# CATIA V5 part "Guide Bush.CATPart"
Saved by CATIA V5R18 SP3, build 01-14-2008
Part number: Moving Part01
Bounding box of the stored display mesh (mm): x -39.998 to 39.998, y 0 to 130, z -39.996 to 39.996
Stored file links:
  E:\#00 CATIA V5 Movie\#03 CATIA V5 Data\#07 KIN\Balance Unit (1)\Guide Bush.CATPart
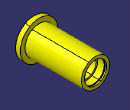
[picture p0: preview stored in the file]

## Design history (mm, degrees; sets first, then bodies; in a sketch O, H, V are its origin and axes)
Body1 "PartBody" (main body)
  Solid1: solid without history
